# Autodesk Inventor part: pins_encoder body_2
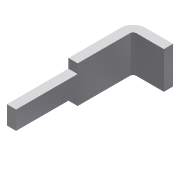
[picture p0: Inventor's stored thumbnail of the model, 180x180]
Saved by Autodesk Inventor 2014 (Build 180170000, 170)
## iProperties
Created: 2015-11
Part Number: pins_encoder body_2
Material: Generic
Document SubType Name: Modeling
Designer: Tom
Density: 1 g/cm^3
Appearance: Default
d2: 0.015 in
d3: 0.090 in
d4: 0.005 in
d6: 0.020 in
d7: 0.060 in
d8: 0.00 deg
d9: 0.030 in
d11: 0.015 in
d12: 0.100 in
d14: 0.00 deg
d10: 0.060 in
Author: Tom
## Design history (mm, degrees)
derived "pins_encoder body.ipt"
  sketch "Sketch2"
    geometry: L1 (0, 0)-(0, 5.08) reference; L2 (0, 3.64)-(1.143, 3.64) reference; L3 (1.143, 3.259)-(0, 3.259) reference; L4 (0, 3.259)-(0, 3.64) reference; L5 (1.27, 3.132)-(1.27, 0.973) reference; L6 (1.27, 0.973)-(1.651, 0.973) reference; L7 (1.651, 3.132)-(1.651, 0.973) reference; A1 r 0.127 centre (1.143, 3.132) between (1.27, 3.132) and (1.143, 3.259) reference; A2 r 0.508 centre (1.143, 3.132) between (1.651, 3.132) and (1.143, 3.64) reference; 2 further points
  sketch "Sketch3"
    geometry: L1 (0, 0)-(0, -1.524) reference; L2 (0, -1.143)-(2.54, -1.143) reference; L3 (2.54, -1.143)-(2.54, -0.381) reference; L4 (2.54, -0.381)-(0, -0.381) reference; L5 (0, -0.381)-(0, -1.143) reference; 1 further point
feature "Solid1::pins_encoder body.ipt"
tag "TaggingFeature1"
workplane "Work Plane2"
body "Solid1"
other parameters: "d2" = 0.381, "d3" = 2.286, "d4" = 0.127, "d6" = 0.508, "d7" = 1.524, "d8" = 0 deg, "d9" = 0.762, "d11" = 0.381, "d12" = 2.54, "d14" = 0 deg, "d10" = 1.524
